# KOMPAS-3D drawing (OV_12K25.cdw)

Referenced files in C:\Documents and Settings\Otto\Рабочий стол\Чертежи\: МРС_Общий вид.cdw
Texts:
  Токарно-винторезный  станок 16К25
  Колесов
  125 1 126 1 127 1 128 0 50 1|SPDS|125 1 126 1 127 1 128 0 50 1
  129 1 130 1 131 1 132 0 50 1|SPDS|129 1 130 1 131 1 132 0 50 1
  Normal
  Рукоятка установки величины подачи и шага резьбы
  Рукоятка установки вида работ: подачи и типа нарезаемой резьбы
  Рукоятка установки числа оборотов шпинделя
  Рукоятка установки нормального, увеличенного шага резьбы и положения при делении многозаходных резьб
  Вводной автоматический выключатель Сигнальная лампа
  Выключатель электронасоса подачи охлаждающей жидкости Указатель нагрузки станка
  Рукоятка установки правой и левой резьбы Рукоятка установки ряда чисел оборотов шпинделя
  Рукоятка управления фрикционной муфтой главного привода (сблокирована с рукояткой 17 )
  Выключатель лампы местного освещения Рукоятка поворота и закрепления индексируемой резцовой головки
  Рукоятка ручного перемещения резцовых салазок суппорта Рукоятка крепления пиноли задней бабки к станине
  Маховик перемещения пиноли задней бабки
  Рукоятка управления фрикционной муфтой главного привода (сблокирована с рукояткой 11)
  Рукоятка включения и выключения гайки ходового винта
  Рукоятка управления механическими перемещениями каретки и поперечных салазок суппорта
  Кнопочная станция включения н выключения электродвигателя главного привода
  Рукоятка ручного перемещения поперечных салазок суппэрта Маховик ручного перемещения каретки
  Кнопка золотника смазки направляющих каретки и поперечных салазок суппорта
  Рукоятка установки величины подачи н шага резьбы и отключения механизма коробки подач при нарезке резьб напрямую
  Рукоятка зажима пиноли задней бабки
  Токарно-винторезный
  станок 16К25
  Шереметьев Н
  Давыденко П.А.
  ИМПБд-01-17
Dimensions and other numbers on the sheet: 2795; 1500; 1240; 5; 4; 3; 2; 16; 15; 14; 19; 20; 21; 18; 17; 1; 8; 9; 11; 13; 12; 10; 7; 1:10; 3095кг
